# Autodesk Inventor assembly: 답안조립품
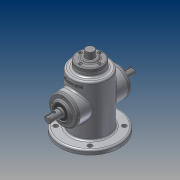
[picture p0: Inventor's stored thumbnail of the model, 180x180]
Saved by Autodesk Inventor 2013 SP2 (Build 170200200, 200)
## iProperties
Created: 2014-12
Part Number: 답안조립품
Document SubType Name: Assembly
Designer: CADB201
Author: CADB201
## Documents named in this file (12)
- C:\Users\CADB201\Desktop\441228V1016\답안조립품.iam
- C:\Users\CADB201\Desktop\441228V1016\본체.ipt
- C:\Users\CADB201\Desktop\441228V1016\커버.ipt
- C:\Users\CADB201\Desktop\441228V1016\편심축.ipt
- C:\Users\CADB201\Desktop\441228V1016\베어링 6002.ipt
- 베어링 6002.ipt
- C:\Users\CADB201\Desktop\441228V1016\슬라이드.ipt
- C:\Users\CADB201\Desktop\441228V1016\상단커버.ipt
- C:\Users\CADB201\Desktop\441228V1016\M3x0.5x8.ipt
- M3x0.5.ipt
- C:\Users\CADB201\Desktop\441228V1016\오일실.ipt
- 오일실.ipt
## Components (12 placed, 1 different names)
1. M3x0.5:2 — 각도:3
2. M3x0.5:4
3. M3x0.5:5
4. M3x0.5:6
5. M3x0.5:3 — 각도:4
6. M3x0.5:7
7. M3x0.5:8
8. M3x0.5:9
9. M3x0.5:1 — 각도:2
10. M3x0.5:10
11. M3x0.5:11
12. M3x0.5:12
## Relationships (3: Angle 3)
- 각도:2 [Angle]: M3x0.5:1
- 각도:3 [Angle]: M3x0.5:2
- 각도:4 [Angle]: M3x0.5:3
